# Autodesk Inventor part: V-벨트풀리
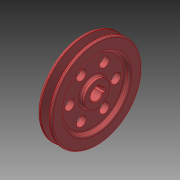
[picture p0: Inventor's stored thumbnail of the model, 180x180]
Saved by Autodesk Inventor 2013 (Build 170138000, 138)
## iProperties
Created: 2010-03
Part Number: V-벨트풀리
Document SubType Name: Modeling
Designer: Administrator
Density: 1 g/cm^3
Material: 일반
Author: Administrator
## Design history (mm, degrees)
sketch "스케치1"
  geometry: L1 (-10, 0)-(10, 0); L2 (10, 0)-(10, 65); L3 (-10, 65)-(-10, 0); L4 (10, 19)-(10, 0); L5 (-10, 65)-(-6.062, 65); L6 (-6.062, 65)-(-2.001, 52.5); L7 (2.001, 52.5)-(6.062, 65); L8 (6.062, 65)-(10, 65); L9 (-2.001, 52.5)-(2.001, 52.5); L10 (-10, 47)-(-4, 47); L11 (-4, 47)-(-4, 18); L12 (-4, 18)-(-10, 18); L13 (-10, 18)-(-10, 47); L14 (10, 47)-(4, 47); L15 (4, 47)-(4, 18); L16 (4, 18)-(10, 18); L17 (10, 18)-(10, 47); 5 further points
  constraints: 34 end point, 6 collinear, 6 horizontal, 5 parallel, 4 point on line, 3 perpendicular, 2 midpoint, 1 coincident, 1 horizontal alignment, 1 vertical alignment
  dimensions: "d0" = 121 diameter of point (-4.6, 60.5) L1; "d1" = 4.5 distance from line of L5 point (-4.6, 60.5); "d2" = 8 distance from line of L9 point (-4.6, 60.5); "d3" = 9.2 distance of point (-4.6, 60.5) point (4.6, 60.5); "d4" = 36 deg angle of L7 L6; "d5" = 10 distance from line of point (0, 52.5) L3; "d8" = 6 distance of L14.start L14.end; "d10" = 29 distance of L14.end L15.end; "d29" = 36 diameter of L16 L1
revolve "회전1" sketch "스케치1" stored, may be unused: angle "d11" = 90 deg
fillet "모깎기1" dims "d12" = 2, "d13" = 1, "d14" = 0.5
fillet "모깎기2" dims "d15" = 3
sketch "스케치2"
  geometry: L1 (-3, 8.485)-(3, 8.485); L2 (3, 8.485)-(3, 11.8); L3 (3, 11.8)-(-3, 11.8); L4 (-3, 11.8)-(-3, 8.485); C1 r 18 at (0, 0) reference; A1 r 9 centre (0, 0) between (-3, 8.485) and (3, 8.485)
  constraints: 8 end point, 2 parallel, 2 point on circle, 1 centre point, 1 concentric, 1 horizontal, 1 perpendicular
  dimensions: "d16" = 18 diameter of A1; "d19" = 2.8 distance edge to line of A1 L3; "d20" = 6 distance of L2.end L3.end
extrude "돌출1" cut sketch "스케치2" stored distance "d17" = 10; taper "d18" = 0 deg
chamfer "모따기1" distance "d30" = 1; stored, may be unused: second distance "d31" = 2, angle "d32" = 45 deg
sketch "스케치4" dims "d33" = 66
  geometry: C1 r 7 at (0, 33); 2 further points
  constraints: 2 vertical alignment, 1 centre point, 1 coincident, 2 other
  dimensions: "d34" = 14 diameter of C1
extrude "돌출2" cut sketch "스케치4" stored distance "d35" = 10; taper "d36" = 0 deg
node "솔리드1"
pattern_circular "원형 패턴1" dims angle "d38" = 360 deg
